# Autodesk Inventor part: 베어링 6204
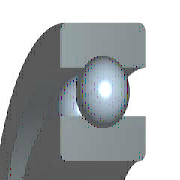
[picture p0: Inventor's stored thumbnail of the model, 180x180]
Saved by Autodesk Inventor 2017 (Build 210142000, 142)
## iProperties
Created: 2012-02
Part Number: 베어링 6204
Material: 강철, 연강
Description: 깊은 그루브 볼 베어링
Document SubType Name: Modeling
Standard: KS B 2023
Designer: mduedu
Standards Organization: KS
Language: ko-KR
Size Designation: 6203 - 17 x 40 x 12
Categories: <MemberInstance><Categories><Category DisplayName="샤프트 부품" InternalName="7f7aeb1f-a693-4053-b835-cee3144e0d98" Mnemonic="SHFT"><Category DisplayName="베어링" Inter
Density: 1 g/cm^3
Appearance: 노란색
IsCustomPart: 1
Author: mduedu
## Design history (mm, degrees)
sketch "스케치" dims "d0" = 7.02 (= -0.26 x WD + 0.26 x BD)
  geometry: L1 (3.49, 16.75)-(10.51, 16.75); L2 (7, 16.75)-(7, 13.24); L3 (7, 16.75)-(7, 20.26); L4 (4.392, 14.401)-(0, 14.401); L5 (0, 10)-(14, 10); L6 (4.392, 19.099)-(0, 19.099); L7 (0, 23.5)-(14, 23.5); L8 (14, 10)-(14, 14.401); L9 (9.608, 14.401)-(14, 14.401); L10 (9.608, 19.099)-(14, 19.099); L11 (14, 23.5)-(14, 19.099); L12 (-2.4, 0)-(14.4, 0) reference; L13 (0, 7.3)-(0, 26.2) reference
  constraints: 22 end point, 4 point on line, 2 collinear, 2 perpendicular, 2 symmetric about line, 1 midpoint, 1 parallel, 14 other
  dimensions: "d9" = 20 diameter of L5 L12 (= WD); "d11" = 47 diameter of L7 L12 (= BD); "d12" = 14 distance between parallel lines of L8 L13 (= KB); "d13" = 28.802 diameter of L9 L12 (= 0.326 x BD + 0.674 x WD)
revolve "본체" stored, may be unused: angle "d6" = 90 deg
revolve "볼" stored, may be unused: angle "d7" = 90 deg
pattern_circular "IDS_ARRAYBALL[SIMPL:T]" dims angle "d3" = 360 deg
body "Solid1"
fillet "모깎기1" dims "d1" = 1 (= KRS)
other parameters: "WD" = 20 [user parameter; used in 5 equation terms], "BD" = 47 [user parameter; used in 5 equation terms], "KB" = 14 [user parameter; used in 1 equation term], "KRS" = 1 [user parameter; used in 1 equation term], "d4" = 0, "d5" = 0, "d8" = 0, "d14" = 0, "d15" = 0, "BBA" = 0 [user parameter], "BC0" = 4750000 [user parameter], "BC" = 9560000 [user parameter], "BR" = 23.5 (= 0.5 x BD) [user parameter]
